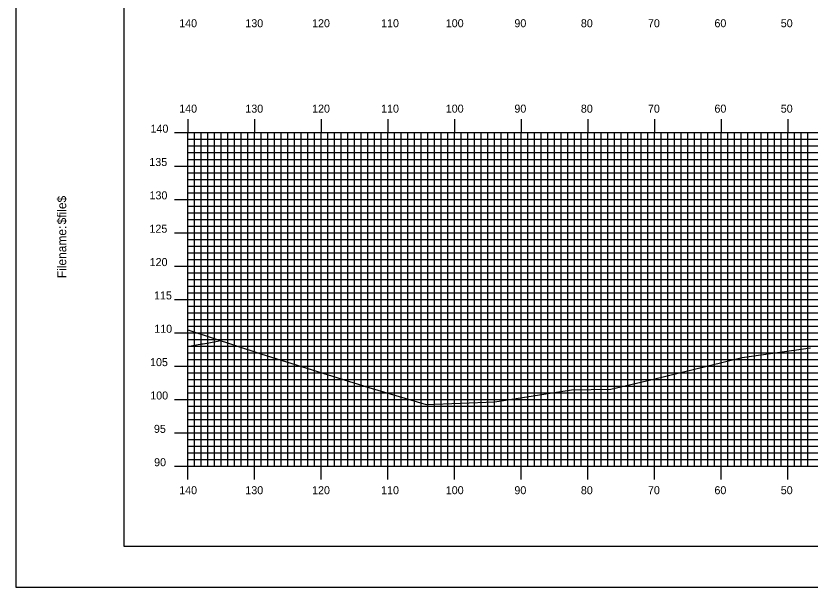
# Model space of a CAD drawing. Extents: x 1755495 to 1755838, y 442591 to 442811.
# Drawn here: x 1755494.8 to 1755613.9, y 442590.5 to 442676.2 of the extents above; entities that cross this region are included whole.
import ezdxf

# ---------------------------------------------------------------- set-up
doc = ezdxf.new("R2010")
doc.units = 0
for name, color, linetype in [('BORDER', 7, 'Continuous'), ('D_Roadway_Centerline', 7, 'Continuous'), ('H_V ANNOTATION', 7, 'Continuous'), ('MAJOR', 7, 'Continuous'), ('MINOR', 7, 'Continuous'), ('PLOT BOUNDARY', 7, 'Continuous'), ('S_Roadway_Centerline', 7, 'Continuous')]:
    doc.layers.add(name, color=color, linetype=linetype)

msp = doc.modelspace()

# ---------------------------------------------------------------- linework, layer by layer
at = {"layer": 'BORDER'}
msp.add_lwpolyline([(1755510.94, 442596.67), (1755830.94, 442596.67), (1755830.94, 442806.67), (1755510.94, 442806.67)], close=True, dxfattribs=at)
at = {"layer": 'D_Roadway_Centerline'}
msp.add_lwpolyline([(1755520.54, 442626.64), (1755520.89, 442626.66), (1755521.03, 442626.68), (1755521.06, 442626.69), (1755522.63, 442626.99), (1755522.82, 442627), (1755523.1, 442627.06), (1755523.12, 442627.06), (1755524.72, 442627.38), (1755524.76, 442627.38), (1755524.99, 442627.43), (1755524.99, 442627.43), (1755525.2, 442627.47), (1755525.2, 442627.47), (1755525.38, 442627.51)], dxfattribs=at)
at = {"layer": 'MAJOR'}
for p, q in [((1755520.54, 442660.67), (1755520.54, 442658.67)), ((1755530.54, 442660.67), (1755530.54, 442658.67)), ((1755540.54, 442660.67), (1755540.54, 442658.67)), ((1755550.54, 442660.67), (1755550.54, 442658.67)), ((1755560.54, 442660.67), (1755560.54, 442658.67)), ((1755570.54, 442660.67), (1755570.54, 442658.67)), ((1755580.54, 442660.67), (1755580.54, 442658.67)), ((1755590.54, 442660.67), (1755590.54, 442658.67)), ((1755600.54, 442660.67), (1755600.54, 442658.67)), ((1755610.54, 442660.67), (1755610.54, 442658.67)), ((1755518.54, 442658.67), (1755520.54, 442658.67)), ((1755520.54, 442658.67), (1755800.54, 442658.67)), ((1755520.54, 442608.67), (1755520.54, 442658.67)), ((1755520.54, 442608.67), (1755520.54, 442658.67)), ((1755520.54, 442658.67), (1755800.54, 442658.67)), ((1755530.54, 442608.67), (1755530.54, 442658.67)), ((1755540.54, 442608.67), (1755540.54, 442658.67)), ((1755550.54, 442608.67), (1755550.54, 442658.67)), ((1755560.54, 442608.67), (1755560.54, 442658.67)), ((1755570.54, 442608.67), (1755570.54, 442658.67)), ((1755580.54, 442608.67), (1755580.54, 442658.67)), ((1755590.54, 442608.67), (1755590.54, 442658.67)), ((1755600.54, 442608.67), (1755600.54, 442658.67)), ((1755610.54, 442608.67), (1755610.54, 442658.67)), ((1755518.54, 442653.67), (1755520.54, 442653.67)), ((1755520.54, 442653.67), (1755800.54, 442653.67)), ((1755518.54, 442648.67), (1755520.54, 442648.67)), ((1755520.54, 442648.67), (1755800.54, 442648.67)), ((1755518.54, 442643.67), (1755520.54, 442643.67)), ((1755520.54, 442643.67), (1755800.54, 442643.67)), ((1755518.54, 442638.67), (1755520.54, 442638.67)), ((1755520.54, 442638.67), (1755800.54, 442638.67)), ((1755518.54, 442633.67), (1755520.54, 442633.67)), ((1755520.54, 442633.67), (1755800.54, 442633.67)), ((1755518.54, 442628.67), (1755520.54, 442628.67)), ((1755520.54, 442628.67), (1755800.54, 442628.67)), ((1755518.54, 442623.67), (1755520.54, 442623.67)), ((1755520.54, 442623.67), (1755800.54, 442623.67)), ((1755518.54, 442618.67), (1755520.54, 442618.67)), ((1755520.54, 442618.67), (1755800.54, 442618.67)), ((1755518.54, 442613.67), (1755520.54, 442613.67)), ((1755520.54, 442613.67), (1755800.54, 442613.67)), ((1755518.54, 442608.67), (1755520.54, 442608.67)), ((1755520.54, 442608.67), (1755800.54, 442608.67)), ((1755520.54, 442608.67), (1755800.54, 442608.67)), ((1755520.54, 442606.66), (1755520.54, 442608.67)), ((1755530.54, 442606.66), (1755530.54, 442608.67)), ((1755540.54, 442606.66), (1755540.54, 442608.67)), ((1755550.54, 442606.66), (1755550.54, 442608.67)), ((1755560.54, 442606.66), (1755560.54, 442608.67)), ((1755570.54, 442606.66), (1755570.54, 442608.67)), ((1755580.54, 442606.66), (1755580.54, 442608.67)), ((1755590.54, 442606.66), (1755590.54, 442608.67)), ((1755600.54, 442606.66), (1755600.54, 442608.67)), ((1755610.54, 442606.66), (1755610.54, 442608.67))]:
    msp.add_line(p, q, dxfattribs=at)
at = {"layer": 'MINOR'}
for p, q in [((1755521.54, 442608.67), (1755521.54, 442658.67)), ((1755522.54, 442608.67), (1755522.54, 442658.67)), ((1755523.54, 442608.67), (1755523.54, 442658.67)), ((1755524.54, 442608.67), (1755524.54, 442658.67)), ((1755525.54, 442608.67), (1755525.54, 442658.67)), ((1755526.54, 442608.67), (1755526.54, 442658.67)), ((1755527.54, 442608.67), (1755527.54, 442658.67)), ((1755528.54, 442608.67), (1755528.54, 442658.67)), ((1755529.54, 442608.67), (1755529.54, 442658.67)), ((1755531.54, 442608.67), (1755531.54, 442658.67)), ((1755532.54, 442608.67), (1755532.54, 442658.67)), ((1755533.54, 442608.67), (1755533.54, 442658.67)), ((1755534.54, 442608.67), (1755534.54, 442658.67)), ((1755535.54, 442608.67), (1755535.54, 442658.67)), ((1755536.54, 442608.67), (1755536.54, 442658.67)), ((1755537.54, 442608.67), (1755537.54, 442658.67)), ((1755538.54, 442608.67), (1755538.54, 442658.67)), ((1755539.54, 442608.67), (1755539.54, 442658.67)), ((1755541.54, 442608.67), (1755541.54, 442658.67)), ((1755542.54, 442608.67), (1755542.54, 442658.67)), ((1755543.54, 442608.67), (1755543.54, 442658.67)), ((1755544.54, 442608.67), (1755544.54, 442658.67)), ((1755545.54, 442608.67), (1755545.54, 442658.67)), ((1755546.54, 442608.67), (1755546.54, 442658.67)), ((1755547.54, 442608.67), (1755547.54, 442658.67)), ((1755548.54, 442608.67), (1755548.54, 442658.67)), ((1755549.54, 442608.67), (1755549.54, 442658.67)), ((1755551.54, 442608.67), (1755551.54, 442658.67)), ((1755552.54, 442608.67), (1755552.54, 442658.67)), ((1755553.54, 442608.67), (1755553.54, 442658.67)), ((1755554.54, 442608.67), (1755554.54, 442658.67)), ((1755555.54, 442608.67), (1755555.54, 442658.67)), ((1755556.54, 442608.67), (1755556.54, 442658.67)), ((1755557.54, 442608.67), (1755557.54, 442658.67)), ((1755558.54, 442608.67), (1755558.54, 442658.67)), ((1755559.54, 442608.67), (1755559.54, 442658.67)), ((1755561.54, 442608.67), (1755561.54, 442658.67)), ((1755562.54, 442608.67), (1755562.54, 442658.67)), ((1755563.54, 442608.67), (1755563.54, 442658.67)), ((1755564.54, 442608.67), (1755564.54, 442658.67)), ((1755565.54, 442608.67), (1755565.54, 442658.67)), ((1755566.54, 442608.67), (1755566.54, 442658.67)), ((1755567.54, 442608.67), (1755567.54, 442658.67)), ((1755568.54, 442608.67), (1755568.54, 442658.67)), ((1755569.54, 442608.67), (1755569.54, 442658.67)), ((1755571.54, 442608.67), (1755571.54, 442658.67)), ((1755572.54, 442608.67), (1755572.54, 442658.67)), ((1755573.54, 442608.67), (1755573.54, 442658.67)), ((1755574.54, 442608.67), (1755574.54, 442658.67)), ((1755575.54, 442608.67), (1755575.54, 442658.67)), ((1755576.54, 442608.67), (1755576.54, 442658.67)), ((1755577.54, 442608.67), (1755577.54, 442658.67)), ((1755578.54, 442608.67), (1755578.54, 442658.67)), ((1755579.54, 442608.67), (1755579.54, 442658.67)), ((1755581.54, 442608.67), (1755581.54, 442658.67)), ((1755582.54, 442608.67), (1755582.54, 442658.67)), ((1755583.54, 442608.67), (1755583.54, 442658.67)), ((1755584.54, 442608.67), (1755584.54, 442658.67)), ((1755585.54, 442608.67), (1755585.54, 442658.67)), ((1755586.54, 442608.67), (1755586.54, 442658.67)), ((1755587.54, 442608.67), (1755587.54, 442658.67)), ((1755588.54, 442608.67), (1755588.54, 442658.67)), ((1755589.54, 442608.67), (1755589.54, 442658.67)), ((1755591.54, 442608.67), (1755591.54, 442658.67)), ((1755592.54, 442608.67), (1755592.54, 442658.67)), ((1755593.54, 442608.67), (1755593.54, 442658.67)), ((1755594.54, 442608.67), (1755594.54, 442658.67)), ((1755595.54, 442608.67), (1755595.54, 442658.67)), ((1755596.54, 442608.67), (1755596.54, 442658.67)), ((1755597.54, 442608.67), (1755597.54, 442658.67)), ((1755598.54, 442608.67), (1755598.54, 442658.67)), ((1755599.54, 442608.67), (1755599.54, 442658.67)), ((1755601.54, 442608.67), (1755601.54, 442658.67)), ((1755602.54, 442608.67), (1755602.54, 442658.67)), ((1755603.54, 442608.67), (1755603.54, 442658.67)), ((1755604.54, 442608.67), (1755604.54, 442658.67)), ((1755605.54, 442608.67), (1755605.54, 442658.67)), ((1755606.54, 442608.67), (1755606.54, 442658.67)), ((1755607.54, 442608.67), (1755607.54, 442658.67)), ((1755608.54, 442608.67), (1755608.54, 442658.67)), ((1755609.54, 442608.67), (1755609.54, 442658.67)), ((1755611.54, 442608.67), (1755611.54, 442658.67)), ((1755612.54, 442608.67), (1755612.54, 442658.67)), ((1755613.54, 442608.67), (1755613.54, 442658.67)), ((1755520.54, 442657.67), (1755800.54, 442657.67)), ((1755520.54, 442657.67), (1755522.55, 442657.67)), ((1755520.54, 442656.67), (1755800.54, 442656.67)), ((1755520.54, 442656.67), (1755522.55, 442656.67)), ((1755520.54, 442655.67), (1755800.54, 442655.67)), ((1755520.54, 442655.67), (1755522.55, 442655.67)), ((1755520.54, 442654.67), (1755800.54, 442654.67)), ((1755520.54, 442654.67), (1755522.55, 442654.67)), ((1755520.54, 442652.67), (1755800.54, 442652.67)), ((1755520.54, 442652.67), (1755522.55, 442652.67)), ((1755520.54, 442651.67), (1755800.54, 442651.67)), ((1755520.54, 442651.67), (1755522.55, 442651.67)), ((1755520.54, 442650.67), (1755800.54, 442650.67)), ((1755520.54, 442650.67), (1755522.55, 442650.67)), ((1755520.54, 442649.67), (1755800.54, 442649.67)), ((1755520.54, 442649.67), (1755522.55, 442649.67)), ((1755520.54, 442647.67), (1755800.54, 442647.67)), ((1755520.54, 442647.67), (1755522.55, 442647.67)), ((1755520.54, 442646.67), (1755800.54, 442646.67)), ((1755520.54, 442646.67), (1755522.55, 442646.67)), ((1755520.54, 442645.67), (1755800.54, 442645.67)), ((1755520.54, 442645.67), (1755522.55, 442645.67)), ((1755520.54, 442644.67), (1755800.54, 442644.67)), ((1755520.54, 442644.67), (1755522.55, 442644.67)), ((1755520.54, 442642.67), (1755800.54, 442642.67)), ((1755520.54, 442642.67), (1755522.55, 442642.67)), ((1755520.54, 442641.67), (1755800.54, 442641.67)), ((1755520.54, 442641.67), (1755522.55, 442641.67)), ((1755520.54, 442640.67), (1755800.54, 442640.67)), ((1755520.54, 442640.67), (1755522.55, 442640.67)), ((1755520.54, 442639.67), (1755800.54, 442639.67)), ((1755520.54, 442639.67), (1755522.55, 442639.67)), ((1755520.54, 442637.67), (1755800.54, 442637.67)), ((1755520.54, 442637.67), (1755522.55, 442637.67)), ((1755520.54, 442636.67), (1755800.54, 442636.67)), ((1755520.54, 442636.67), (1755522.55, 442636.67)), ((1755520.54, 442635.67), (1755800.54, 442635.67)), ((1755520.54, 442635.67), (1755522.55, 442635.67)), ((1755520.54, 442634.67), (1755800.54, 442634.67)), ((1755520.54, 442634.67), (1755522.55, 442634.67)), ((1755520.54, 442632.67), (1755800.54, 442632.67)), ((1755520.54, 442632.67), (1755522.55, 442632.67)), ((1755520.54, 442631.67), (1755800.54, 442631.67)), ((1755520.54, 442631.67), (1755522.55, 442631.67)), ((1755520.54, 442630.67), (1755800.54, 442630.67)), ((1755520.54, 442630.67), (1755522.55, 442630.67)), ((1755520.54, 442629.67), (1755800.54, 442629.67)), ((1755520.54, 442629.67), (1755522.55, 442629.67)), ((1755520.54, 442627.67), (1755800.54, 442627.67)), ((1755520.54, 442627.67), (1755522.55, 442627.67)), ((1755520.54, 442626.67), (1755800.54, 442626.67)), ((1755520.54, 442626.67), (1755522.55, 442626.67)), ((1755520.54, 442625.67), (1755800.54, 442625.67)), ((1755520.54, 442625.67), (1755522.55, 442625.67)), ((1755520.54, 442624.67), (1755800.54, 442624.67)), ((1755520.54, 442624.67), (1755522.55, 442624.67)), ((1755520.54, 442622.67), (1755800.54, 442622.67)), ((1755520.54, 442622.67), (1755522.55, 442622.67)), ((1755520.54, 442621.67), (1755800.54, 442621.67)), ((1755520.54, 442621.67), (1755522.55, 442621.67)), ((1755520.54, 442620.67), (1755800.54, 442620.67)), ((1755520.54, 442620.67), (1755522.55, 442620.67)), ((1755520.54, 442619.67), (1755800.54, 442619.67)), ((1755520.54, 442619.67), (1755522.55, 442619.67)), ((1755520.54, 442617.67), (1755800.54, 442617.67)), ((1755520.54, 442617.67), (1755522.55, 442617.67)), ((1755520.54, 442616.67), (1755800.54, 442616.67)), ((1755520.54, 442616.67), (1755522.55, 442616.67)), ((1755520.54, 442615.67), (1755800.54, 442615.67)), ((1755520.54, 442615.67), (1755522.55, 442615.67)), ((1755520.54, 442614.67), (1755800.54, 442614.67)), ((1755520.54, 442614.67), (1755522.55, 442614.67)), ((1755520.54, 442612.67), (1755800.54, 442612.67)), ((1755520.54, 442612.67), (1755522.55, 442612.67)), ((1755520.54, 442611.67), (1755800.54, 442611.67)), ((1755520.54, 442611.67), (1755522.55, 442611.67)), ((1755520.54, 442610.67), (1755800.54, 442610.67)), ((1755520.54, 442610.67), (1755522.55, 442610.67)), ((1755520.54, 442609.67), (1755800.54, 442609.67)), ((1755520.54, 442609.67), (1755522.55, 442609.67))]:
    msp.add_line(p, q, dxfattribs=at)
at = {"layer": 'PLOT BOUNDARY'}
msp.add_lwpolyline([(1755494.76, 442590.55), (1755834.76, 442590.55), (1755834.76, 442810.55), (1755494.76, 442810.55)], close=True, dxfattribs=at)
at = {"layer": 'S_Roadway_Centerline'}
msp.add_lwpolyline([(1755520.54, 442629.13), (1755527.67, 442626.75), (1755531.49, 442625.53), (1755547.69, 442620.45), (1755556.31, 442617.91), (1755566.57, 442618.34), (1755578.09, 442620.1), (1755583.97, 442620.22), (1755590.18, 442621.68), (1755598.56, 442623.74), (1755603.68, 442624.99), (1755613.92, 442626.39)], dxfattribs=at)

# ---------------------------------------------------------------- texts
at = {"layer": 'BORDER'}
for s, p in [('$file$', (1755502.31, 442644.92)), ('$file$', (1755502.31, 442644.92)), ('Filename:', (1755502.31, 442636.86)), ('Filename:', (1755502.31, 442636.86))]:
    msp.add_text(s, height=1.339, rotation=90, dxfattribs=at).set_placement(p)
at = {"layer": 'H_V ANNOTATION'}
for s, p in [('140', (1755519.25, 442674.47)), ('130', (1755529.17, 442674.47)), ('120', (1755539.18, 442674.47)), ('110', (1755549.53, 442674.47)), ('100', (1755559.23, 442674.47)), ('90', (1755569.52, 442674.47)), ('80', (1755579.49, 442674.47)), ('70', (1755589.55, 442674.47)), ('60', (1755599.52, 442674.47)), ('50', (1755609.47, 442674.47)), ('140', (1755519.25, 442661.67)), ('130', (1755529.17, 442661.67)), ('120', (1755539.18, 442661.67)), ('110', (1755549.53, 442661.67)), ('100', (1755559.23, 442661.67)), ('90', (1755569.52, 442661.67)), ('80', (1755579.49, 442661.67)), ('70', (1755589.55, 442661.67)), ('60', (1755599.52, 442661.67)), ('50', (1755609.47, 442661.67)), ('140', (1755514.95, 442658.67)), ('135', (1755514.77, 442653.67)), ('130', (1755514.8, 442648.67)), ('125', (1755514.79, 442643.67)), ('120', (1755514.82, 442638.67)), ('115', (1755515.48, 442633.67)), ('110', (1755515.51, 442628.67)), ('105', (1755514.88, 442623.67)), ('100', (1755514.91, 442618.67)), ('95', (1755515.46, 442613.67)), ('90', (1755515.49, 442608.67)), ('140', (1755519.25, 442604.47)), ('130', (1755529.17, 442604.47)), ('120', (1755539.18, 442604.47)), ('110', (1755549.53, 442604.47)), ('100', (1755559.23, 442604.47)), ('90', (1755569.52, 442604.47)), ('80', (1755579.49, 442604.47)), ('70', (1755589.55, 442604.47)), ('60', (1755599.52, 442604.47)), ('50', (1755609.47, 442604.47))]:
    msp.add_text(s, height=1.2, dxfattribs=at).set_placement(p)
at = {"layer": 'MAJOR'}
msp.add_text('-', height=0.012, dxfattribs=at).set_placement((1755520.53, 442608.67))

doc.saveas('drawing.dxf')
